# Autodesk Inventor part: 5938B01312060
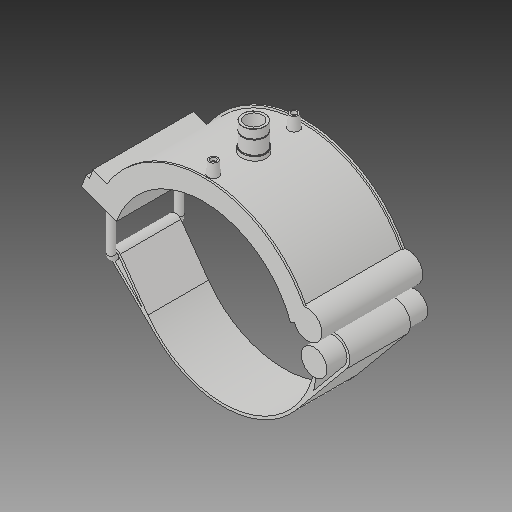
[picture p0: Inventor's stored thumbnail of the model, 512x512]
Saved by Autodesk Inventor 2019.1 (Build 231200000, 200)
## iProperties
Created: 2017-07
Part Number: 5938B01312060
Material: Generic
Description: PLASSON TRANSITION SADDLE 12''IPS x 1"NPT
Document SubType Name: Modeling
Designer: KIM
Density: 1 g/cm^3
Appearance: Default
Author: KIM
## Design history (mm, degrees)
derived "5938B.ipt"
feature "Solid1::5938B.ipt"
tag "TaggingFeature1"
body "Solid1"
other parameters: "d0" = 323.4, "d1" = 388.08, "d2" = 487.045, "d3" = 80.85, "d4" = 176.022, "d5" = 0, "d40" = 201.8016, "d41" = 42.4074, "d43" = 0, "d45" = 0, "d47" = 240.776, "d48" = 39.3783, "d50" = 0, "d78" = 216.04, "d79" = 15, "d80" = 70.4088, "d82" = 5 deg, "d84" = 4, "d85" = 14, "d86" = 0, "d87" = 3, "d88" = 0, "d96" = 395.8416, "d97" = 3.52044, "d98" = 0, "d102" = 0.90873, "d103" = 30.291, "d104" = 28.0416, "d105" = 0, "d106" = 24.2328, "d108" = 0, "d109" = -15.57867, "d111" = 0.5, "d112" = 0.5, "d113" = 0, "d114" = 0.5, "d117" = 0.30291, "d120" = 140 deg, "d121" = 24.228, "d122" = 20 deg, "d123" = 1552.32, "d124" = 232.848, "d126" = 0, "d143" = 333.102, "d145" = 49.75385, "d149" = 4.851, "d150" = 54.72923, "d153" = 176.022, "d154" = 0, "d156" = 194.04, "d157" = 160 deg, "d159" = 12.936, "d161" = 4.851, "d162" = 105.6132, "d163" = 0, "d164" = 161.7, "d167" = 32.34, "d168" = 189.30732, "d170" = 4.851, "d172" = 0, "d173" = 1, "d175" = 161.7, "d176" = 20 deg, "d177" = 22.638, "d178" = 64.68, "d180" = 0, "d183" = 25.872, "d184" = 18.1104, "d185" = 57.20715, "d186" = 57.20715, "d187" = 194.04, "d188" = 19.404, "d189" = 22.638, "d190" = 0, "d191" = 232.848, "d193" = 12.936, "d194" = 6.6297, "d195" = 90 deg, "d197" = 0, "d199" = 0, "d_" = 323.4, "B_" = 194.818, "H_" = 46.736, "L_" = 176.022, "d_t" = 6, "G_" = 30.291, "d148" = 4.851, "d160" = 4.851, "d169" = 4.851, "d192" = 12.936
